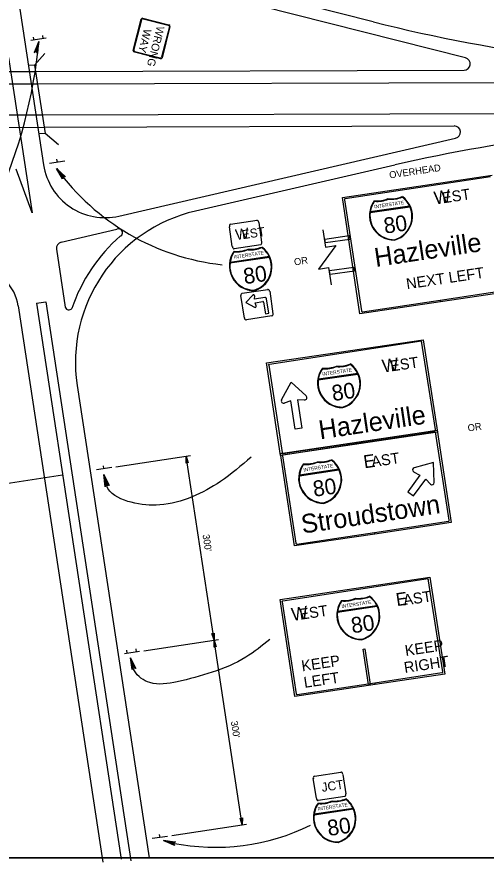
# Model space of a CAD drawing. Extents: x 644898 to 648326, y 298294 to 300670.
# Drawn here: x 647835.4 to 648038.7, y 300089.7 to 300456 of the extents above; entities that cross this region are included whole.
import ezdxf

# ---------------------------------------------------------------- set-up
doc = ezdxf.new("R2010")
doc.units = 0
doc.layers.add('1', color=7, linetype='Continuous')
doc.layers.add('2', color=7, linetype='Continuous')

msp = doc.modelspace()

# ---------------------------------------------------------------- linework, layer by layer
at = {"layer": '1'}
for p, q in [((648247.32, 300091.49), (647461.32, 300091.49)), ((647461.32, 300091.49), (648047.32, 300091.49))]:
    msp.add_line(p, q, dxfattribs=at)
at = {"layer": '2'}
for p, q in [((647989.82, 300453.87), (647844.32, 300490.74)), ((648029.82, 300438.24), (647855.82, 300482.24)), ((647835.95, 300464.24), (647846.95, 300391.87)), ((647885.82, 300441.37), (647889.2, 300454.99)), ((647886.07, 300441.49), (647889.45, 300454.87)), ((647889.95, 300455.37), (647901.2, 300452.49)), ((647890.07, 300455.12), (647900.95, 300452.37)), ((647901.45, 300451.74), (647898.07, 300438.49)), ((647901.7, 300451.87), (647898.32, 300438.24)), ((647848.07, 300446.74), (647841.45, 300445.74)), ((647842.82, 300445.87), (647842.57, 300447.24)), ((647846.82, 300446.49), (647846.57, 300447.87)), ((647893.7, 300446.62), (647893.7, 300446.62)), ((647831.79, 300438.36), (647842.02, 300371.06)), ((647847.45, 300440.12), (647843.07, 300434.99)), ((647897.57, 300437.87), (647886.32, 300440.74)), ((647897.45, 300438.12), (647886.45, 300440.87)), ((647843.07, 300434.99), (647840.4, 300434.97)), ((647843.07, 300434.99), (647847.57, 300405.49)), ((647817.8, 300432.33), (647843.57, 300432.37)), ((647840.82, 300432.37), (647840.82, 300432.37)), ((647843.57, 300432.37), (648029.2, 300432.87)), ((647818.62, 300426.96), (647844.32, 300426.99)), ((647844.32, 300426.99), (648247.32, 300428.13)), ((647820.68, 300413.46), (647846.32, 300413.49)), ((647846.32, 300413.49), (648247.32, 300414.76)), ((647847.2, 300408.12), (648024.95, 300408.74)), ((647821.5, 300408.09), (647847.2, 300408.12)), ((647836.32, 300408.12), (647836.32, 300408.12)), ((647844.45, 300408.12), (647844.45, 300408.12)), ((647847.57, 300405.49), (647844.91, 300405.31)), ((647853.45, 300400.49), (647847.57, 300405.49)), ((647879.57, 300369.62), (648025.45, 300403.37)), ((647852.95, 300392.99), (647852.7, 300394.37)), ((647856.2, 300393.49), (647849.57, 300392.49)), ((647912.82, 300371.87), (647999.2, 300391.87)), ((647842.02, 300371.06), (647835, 300390.04)), ((647976.44, 300377.72), (648041.41, 300387.38)), ((647984.05, 300327.32), (647976.43, 300377.72)), ((647977.35, 300376.73), (647984.69, 300328.54)), ((647990.41, 300376.05), (647990.41, 300376.05)), ((647996.42, 300376.97), (647996.42, 300376.97)), ((648002.34, 300377.86), (648002.34, 300377.86)), ((647988.51, 300371.18), (648005.65, 300373.72)), ((648005.58, 300373.99), (647988.54, 300371.47)), ((647928.7, 300356.49), (647927.45, 300364.99)), ((647927.95, 300366.12), (647939.45, 300367.87)), ((647940.2, 300366.87), (647941.45, 300358.37)), ((647854.57, 300358.37), (647878.7, 300363.99)), ((647934.45, 300361.62), (647934.45, 300361.62)), ((647967.99, 300363.64), (647969.12, 300356.22)), ((647967.99, 300363.64), (647969.12, 300356.22)), ((647941.07, 300357.24), (647929.57, 300355.49)), ((647852.57, 300355.37), (647856.32, 300330.12)), ((647929.7, 300354.24), (647929.7, 300354.24)), ((647935.57, 300355.12), (647935.57, 300355.12)), ((647941.45, 300355.99), (647941.45, 300355.99)), ((647927.7, 300349.37), (647944.82, 300351.87)), ((647944.7, 300352.12), (647927.82, 300349.49)), ((647936.95, 300346.37), (647936.95, 300346.37)), ((647970.48, 300347.32), (647971.61, 300339.91)), ((647933.95, 300325.49), (647932.45, 300335.24)), ((647933.95, 300325.49), (647932.45, 300335.24)), ((647933.07, 300336.24), (647944.07, 300337.87)), ((647933.07, 300336.24), (647944.07, 300337.87)), ((647937.57, 300335.37), (647934.57, 300332.24)), ((647944.95, 300337.12), (647946.32, 300327.37)), ((647944.95, 300337.12), (647946.32, 300327.37)), ((648018.78, 300333.23), (648047.9, 300337.67)), ((648049.11, 300337), (648018.89, 300332.5)), ((647843.83, 300331.92), (647847.96, 300332.54)), ((647843.83, 300331.92), (647880.58, 300090.92)), ((647847.96, 300332.54), (647884.79, 300090.29)), ((647934.57, 300332.24), (647938.32, 300330.12)), ((647938.32, 300333.62), (647938.45, 300335.12)), ((647942.82, 300334.37), (647938.32, 300333.62)), ((647938.7, 300332.12), (647941.95, 300332.62)), ((647939.07, 300330.74), (647938.7, 300332.12)), ((647942.2, 300332.37), (647943.07, 300327.37)), ((647943.57, 300333.74), (647943.57, 300333.74)), ((647944.57, 300327.62), (647943.57, 300333.74)), ((648018.89, 300332.5), (647984.05, 300327.32)), ((647985.09, 300328.16), (648018.78, 300333.23)), ((648018.89, 300332.5), (648018.78, 300333.23)), ((648018.78, 300333.23), (648018.89, 300332.5)), ((647835.92, 300330.71), (647872.67, 300089.71)), ((647939.45, 300331.24), (647939.45, 300331.24)), ((647939.45, 300331.24), (647939.45, 300331.24)), ((647945.82, 300326.37), (647934.82, 300324.74)), ((647945.82, 300326.37), (647934.82, 300324.74)), ((647943.07, 300327.37), (647944.57, 300327.62)), ((647943.58, 300306.01), (648011.47, 300316.1)), ((648016.79, 300277.11), (648010.75, 300315.43)), ((648011.47, 300316.1), (648017.64, 300276.08)), ((647949.66, 300265.97), (647943.58, 300306.02)), ((647944.49, 300305.02), (647950.3, 300267.2)), ((647967.89, 300303.5), (647967.89, 300303.5)), ((647973.9, 300304.42), (647973.9, 300304.42)), ((647966, 300298.64), (647983.13, 300301.18)), ((647983.07, 300301.45), (647966.02, 300298.93)), ((647861.57, 300296.24), (647892.7, 300091.49)), ((647950.06, 300290.1), (647954.3, 300297.69)), ((647954.3, 300297.69), (647960.71, 300291.71)), ((647954.1, 300289.6), (647951.26, 300288.53)), ((647955.92, 300277.3), (647954.1, 300289.6)), ((647956.97, 300290.01), (647958.8, 300277.73)), ((647960.1, 300289.95), (647956.97, 300290.01)), ((647949.55, 300266.74), (648017.51, 300276.84)), ((647958.8, 300277.73), (647955.92, 300277.3)), ((647984.39, 300271.88), (648016.4, 300276.75)), ((648017.51, 300276.84), (648023.6, 300236.81)), ((648017.64, 300276.08), (647984.51, 300271.1)), ((648022.76, 300237.83), (648016.72, 300276.16)), ((647984.5, 300271.15), (647949.66, 300265.97)), ((647950.7, 300266.81), (647984.39, 300271.88)), ((647984.51, 300271.1), (647984.39, 300271.88)), ((647984.39, 300271.88), (647984.5, 300271.15)), ((647878.32, 300260.99), (647910.57, 300265.87)), ((647920.82, 300185.87), (647908.7, 300265.62)), ((647955.62, 300226.7), (647949.55, 300266.74)), ((647950.46, 300265.75), (647956.26, 300227.93)), ((647959.73, 300262.03), (647959.73, 300262.03)), ((647965.73, 300262.95), (647965.73, 300262.95)), ((648015.96, 300262.92), (648007.5, 300260.63)), ((648016.19, 300254.23), (648015.96, 300262.92)), ((647867.2, 300259.24), (647867.2, 300259.24)), ((647876.45, 300260.74), (647869.82, 300259.74)), ((647873.07, 300260.24), (647872.95, 300261.49)), ((647957.83, 300257.16), (647974.96, 300259.7)), ((647974.9, 300259.97), (647957.85, 300257.45)), ((648007.28, 300258.8), (648010.02, 300257.43)), ((647762.2, 300243.37), (647855.07, 300257.49)), ((648010.02, 300257.43), (648004.85, 300250.15)), ((648007.21, 300248.37), (648012.53, 300255.6)), ((648012.53, 300255.6), (648014.59, 300253.54)), ((648004.85, 300250.15), (648007.21, 300248.37)), ((647990.36, 300232.61), (648022.37, 300237.48)), ((648023.6, 300236.81), (647990.47, 300231.83)), ((647990.47, 300231.88), (647955.62, 300226.7)), ((647956.66, 300227.54), (647990.36, 300232.61)), ((647990.47, 300231.83), (647990.36, 300232.61)), ((647990.36, 300232.61), (647990.47, 300231.88)), ((647949.4, 300203.48), (648014.37, 300213.14)), ((648019.99, 300172.14), (648013.65, 300212.47)), ((648014.37, 300213.14), (648020.83, 300171.13)), ((647955.77, 300161.45), (647949.4, 300203.49)), ((647982.25, 300203.79), (647982.25, 300203.79)), ((647950.31, 300202.5), (647956.47, 300162.68)), ((647974.35, 300198.01), (647991.48, 300200.55)), ((647991.42, 300200.81), (647974.37, 300198.29)), ((647976.24, 300202.87), (647976.24, 300202.87)), ((647890.45, 300181.24), (647922.7, 300186.24)), ((647933.07, 300105.87), (647920.82, 300185.87)), ((647883.2, 300180.24), (647883.07, 300181.49)), ((647887.2, 300180.74), (647887.07, 300182.12)), ((647879.32, 300179.62), (647879.32, 300179.62)), ((647888.57, 300180.99), (647881.95, 300179.99)), ((647990.51, 300167.36), (648019.6, 300171.86)), ((648020.83, 300171.13), (647990.62, 300166.63)), ((647956.82, 300162.28), (647990.51, 300167.36)), ((647990.62, 300166.63), (647990.51, 300167.36)), ((647990.51, 300167.36), (647990.62, 300166.63)), ((647990.62, 300166.63), (647955.77, 300161.45)), ((647964.32, 300126.99), (647975.82, 300128.74)), ((647976.57, 300127.74), (647977.95, 300119.24)), ((647965.2, 300117.37), (647963.82, 300125.87)), ((647970.82, 300122.49), (647970.82, 300122.49)), ((647977.45, 300118.12), (647965.95, 300116.37)), ((647971.95, 300115.99), (647971.95, 300115.99)), ((647977.95, 300116.87), (647977.95, 300116.87)), ((647981.07, 300112.99), (647964.2, 300110.49)), ((647964.2, 300110.24), (647981.2, 300112.74)), ((647966.07, 300115.12), (647966.07, 300115.12)), ((647902.57, 300101.24), (647934.95, 300106.12)), ((647900.7, 300100.87), (647894.07, 300099.87)), ((647897.45, 300100.37), (647897.2, 300101.74)), ((647891.45, 300099.87), (647891.45, 300099.87)), ((647891.45, 300099.49), (647891.45, 300099.49))]:
    msp.add_line(p, q, dxfattribs=at)
for points in [[(647844.23, 300440.45), (647843.9, 300440.76), (647844.89, 300445.34), (647844.23, 300440.45), (647844.44, 300440.16), (647844.89, 300445.34), (647843.52, 300440.82), (647843.13, 300440.76), (647844.89, 300445.34), (647842.84, 300440.55), (647843.13, 300440.76)], [(647855.2, 300386.12), (647855.32, 300386.49), (647852.57, 300390.24), (647855.2, 300386.12), (647855.2, 300385.74), (647852.57, 300390.24), (647855.7, 300386.74), (647856.07, 300386.87), (647852.57, 300390.24), (647856.45, 300386.74), (647856.07, 300386.87)], [(648040.68, 300386.7), (647977.64, 300377.08)], [(647969.12, 300356.22), (647973.57, 300356.9), (647966.03, 300346.65), (647970.48, 300347.32)], [(648010.75, 300315.43), (647944.78, 300305.37)], [(648016.71, 300276.16), (647950.75, 300266.1)], [(647908.77, 300262.74), (647908.96, 300262.88), (647908.7, 300265.62), (647908.77, 300262.74), (647908.67, 300262.58), (647908.7, 300265.62), (647909.25, 300262.93), (647909.46, 300262.86), (647908.7, 300265.62), (647909.62, 300262.73), (647909.46, 300262.86)], [(647873.82, 300252.74), (647874.07, 300252.99), (647873.07, 300257.62), (647873.82, 300252.74), (647873.7, 300252.37), (647873.07, 300257.62), (647874.57, 300253.12), (647874.95, 300253.12), (647873.07, 300257.62), (647875.32, 300252.87), (647874.95, 300253.12)], [(648013.65, 300212.47), (647950.6, 300202.85)], [(647920.75, 300188.74), (647920.56, 300188.61), (647920.82, 300185.87), (647920.75, 300188.74), (647920.85, 300188.91), (647920.82, 300185.87), (647920.28, 300188.56), (647920.06, 300188.63), (647920.82, 300185.87), (647919.9, 300188.76), (647920.06, 300188.63)], [(647920.9, 300182.99), (647921.09, 300183.13), (647920.82, 300185.87), (647920.9, 300182.99), (647920.8, 300182.83), (647920.82, 300185.87), (647921.37, 300183.18), (647921.59, 300183.11), (647920.82, 300185.87), (647921.75, 300182.98), (647921.59, 300183.11)], [(647885.45, 300173.37), (647885.82, 300173.62), (647884.57, 300178.24), (647885.45, 300173.37), (647885.32, 300173.12), (647884.57, 300178.24), (647886.2, 300173.87), (647886.57, 300173.74), (647884.57, 300178.24), (647886.95, 300173.62), (647886.57, 300173.74)], [(647933, 300108.75), (647932.81, 300108.61), (647933.07, 300105.87), (647933, 300108.75), (647933.1, 300108.91), (647933.07, 300105.87), (647932.52, 300108.56), (647932.31, 300108.63), (647933.07, 300105.87), (647932.15, 300108.76), (647932.31, 300108.63)], [(647903.52, 300097.23), (647903.4, 300097.61), (647898.97, 300099.03), (647903.52, 300097.23), (647903.74, 300096.93), (647898.97, 300099.03), (647903.55, 300098.03), (647903.78, 300098.35), (647898.97, 300099.03), (647904.16, 300098.47), (647903.78, 300098.35)]]:
    msp.add_lwpolyline(points, dxfattribs=at)
for points in [[(647979.6, 300359.56), (647969.06, 300358), (647968.8, 300359.71), (647979.35, 300361.28)], [(647981.64, 300345.86), (647971.09, 300344.3), (647970.84, 300346.01), (647981.38, 300347.58)], [(647988.52, 300166.77), (647987.69, 300166.64), (647985.4, 300182.05), (647986.23, 300182.17)]]:
    msp.add_lwpolyline(points, close=True, dxfattribs=at)
for centre, radius, start, end in [((648154.92, 301105.15), 671.88, 255.77937, 270.1682), ((647629.05, 300465.34), 216.77, 316.8838, 354.7037), ((648029.16, 300435.59), 2.69, 270.1683, 75.7793), ((648150.55, 299737.19), 671.88, 90.1683, 103.0152), ((648024.9, 300406.01), 2.69, 283.0152, 90.1683), ((647873.54, 300395.85), 26.87, 188.6538, 283.0152), ((647935.45, 300450.26), 102.28, 215.9181, 263.7348), ((647927.94, 300306.37), 67.19, 103.0152, 188.6538), ((647927.94, 300306.37), 72.56, 131.1224, 161.2817), ((647879.49, 300362.47), 1.67, 290.9294, 117.2399), ((647855.18, 300355.75), 2.69, 103.0154, 188.6538), ((647938.18, 300348.07), 10.73, 143.6538, 270.5237), ((647938.18, 300348.07), 10.51, 144.3462, 171.8611), ((647930.74, 300366.7), 12.33, 264.4038, 292.9038), ((647930.74, 300366.7), 12.56, 264.9943, 292.6428), ((647936.74, 300367.61), 12.33, 264.4038, 292.9038), ((647936.74, 300367.61), 12.56, 264.6648, 292.3133), ((647935.18, 300347.61), 10.73, 286.7839, 53.6538), ((647935.18, 300347.61), 10.51, 25.4466, 52.9614), ((647935.18, 300347.61), 10.51, 286.7839, 24.1669), ((647816.01, 300327.69), 20.16, 8.6538, 80.3831), ((647938.18, 300348.07), 10.51, 173.1407, 270.5237), ((647937.91, 300335.08), 0.502, 358.1291, 138.7947), ((647941.98, 300332.36), 0.269, 8.6538, 98.6538), ((647942.92, 300333.68), 0.672, 8.6538, 98.6538), ((647857.91, 300330.62), 1.63, 197.7979, 323.4245), ((647938.62, 300330.59), 0.502, 236.4996, 20.4062), ((648007.75, 300259.69), 0.915, 103.9183, 245.5492), ((648015.29, 300254.14), 0.915, 225, 1.3737), ((647967.13, 300127.58), 12.33, 264.4038, 292.9038), ((647967.13, 300127.58), 12.56, 264.9943, 292.6428), ((647973.14, 300128.49), 12.33, 264.4038, 292.9038), ((647973.14, 300128.49), 12.56, 264.6648, 292.3133), ((647971.57, 300108.49), 10.73, 286.7839, 53.6538), ((647971.57, 300108.49), 10.51, 25.4466, 52.9614), ((647974.58, 300108.95), 10.73, 143.6538, 270.5237), ((647974.58, 300108.95), 10.51, 144.3462, 171.8611), ((647971.57, 300108.49), 10.51, 286.7839, 24.1669), ((647974.58, 300108.95), 10.51, 173.1407, 270.5237), ((647921.32, 300190.06), 93.92, 258.636, 296.1278)]:
    msp.add_arc(centre, radius, start, end, dxfattribs=at)
for centre, major_axis, ratio, start_param, end_param in [((647889.85, 300454.88), (-0.625, 0.158), 0.777833, 4.712389, 6.283185), ((647890, 300454.69), (-0.578, 0.147), 0.777833, 4.712389, 6.283185), ((647900.88, 300451.93), (-0.578, 0.147), 0.777833, 3.141593, 4.712389), ((647901.1, 300452.02), (-0.625, 0.158), 0.777833, 3.141593, 4.712389), ((647886.4, 300441.26), (0.625, -0.158), 0.777833, 3.141593, 4.712389), ((647886.62, 300441.36), (0.578, -0.147), 0.777833, 3.141593, 4.712389), ((647897.5, 300438.6), (0.578, -0.147), 0.777833, 4.712389, 6.283185), ((647897.65, 300438.41), (0.625, -0.158), 0.777833, 4.712389, 6.283185), ((647977.67, 300376.76), (-0.388, 0), 0.989072, 4.856969, 6.450662), ((647999, 300369.94), (-10.85, 0), 0.989072, 5.647198, 7.861496), ((647999, 300369.94), (-10.62, 0), 0.989072, 5.659282, 6.139508), ((647991.51, 300388.58), (-12.46, 0), 0.989072, 1.471498, 1.968918), ((647991.51, 300388.58), (-12.69, 0), 0.989072, 1.481804, 1.964361), ((647997.58, 300389.48), (12.46, 0), 0.989072, 4.61309, 5.11051), ((647997.58, 300389.48), (12.69, 0), 0.989072, 4.617647, 5.100204), ((647995.97, 300369.48), (10.85, 0), 0.989072, 5.003697, 7.217995), ((647995.97, 300369.48), (10.62, 0), 0.989072, 0.4425, 0.922725), ((647995.97, 300369.48), (10.62, 0), 0.989072, 5.003697, 6.703352), ((647999, 300369.94), (-10.62, 0), 0.989072, 6.161841, 7.861496), ((647928.1, 300365.04), (0.16, -1.06), 0.6, 3.141593, 4.712389), ((647939.58, 300366.79), (-0.16, 1.06), 0.6, 4.712389, 6.283185), ((647940.87, 300358.29), (-0.16, 1.06), 0.6, 3.141593, 4.712389), ((647929.4, 300356.54), (0.16, -1.06), 0.6, 4.712389, 6.283185), ((647933.2, 300335.3), (0.14, -0.921), 0.769266, 3.141593, 4.712389), ((647933.2, 300335.3), (0.14, -0.921), 0.769266, 3.141593, 4.712389), ((647944.19, 300336.98), (-0.14, 0.921), 0.769266, 4.712389, 6.283185), ((647944.19, 300336.98), (-0.14, 0.921), 0.769266, 4.712389, 6.283185), ((647985.05, 300328.57), (-0.402, -0.077), 0.953585, 6.234444, 7.82518), ((647934.67, 300325.63), (0.14, -0.921), 0.769266, 4.712389, 6.283185), ((647934.67, 300325.63), (0.14, -0.921), 0.769266, 4.712389, 6.283185), ((647945.66, 300327.3), (-0.14, 0.921), 0.769266, 3.141593, 4.712389), ((647945.66, 300327.3), (-0.14, 0.921), 0.769266, 3.141593, 4.712389), ((648010.5, 300314.89), (-0.386, 0), 0.994065, 3.283634, 4.860778), ((647944.82, 300305.05), (-0.388, 0), 0.989072, 4.856969, 6.450662), ((647976.49, 300297.39), (-10.85, 0), 0.989072, 5.647198, 7.861496), ((647976.49, 300297.39), (-10.62, 0), 0.989072, 5.659282, 6.139508), ((647969, 300316.03), (-12.46, 0), 0.989072, 1.471498, 1.968918), ((647969, 300316.03), (-12.69, 0), 0.989072, 1.481804, 1.964361), ((647975.06, 300316.94), (12.46, 0), 0.989072, 4.61309, 5.11051), ((647975.06, 300316.94), (12.69, 0), 0.989072, 4.617647, 5.100204), ((647973.45, 300296.94), (10.85, 0), 0.989072, 5.003697, 7.217995), ((647973.45, 300296.94), (10.62, 0), 0.989072, 0.4425, 0.922725), ((647976.49, 300297.39), (-10.62, 0), 0.989072, 6.161841, 7.861496), ((647973.45, 300296.94), (10.62, 0), 0.989072, 5.003697, 6.703352), ((647960.04, 300290.96), (-0.02, 1.02), 0.989072, 3.073775, 5.58542), ((647950.97, 300289.58), (-0.02, 1.02), 0.989072, 1.007506, 3.462583), ((648016.38, 300277.06), (0.395, 0.011), 0.92315, 4.838085, 6.411533), ((648016.46, 300275.62), (-0.386, 0), 0.994065, 3.283634, 4.860778), ((647950.65, 300267.24), (-0.352, -0.214), 0.980321, 5.879464, 7.4702), ((647950.78, 300265.78), (-0.388, 0), 0.989072, 4.856969, 6.450662), ((647968.32, 300255.92), (-10.85, 0), 0.989072, 5.647198, 7.861496), ((647968.32, 300255.92), (-10.62, 0), 0.989072, 5.659282, 6.139508), ((647960.83, 300274.56), (-12.46, 0), 0.989072, 1.471498, 1.968918), ((647960.83, 300274.56), (-12.69, 0), 0.989072, 1.481804, 1.964361), ((647966.89, 300275.46), (12.46, 0), 0.989072, 4.61309, 5.11051), ((647966.89, 300275.46), (12.69, 0), 0.989072, 4.617647, 5.100204), ((647965.28, 300255.46), (10.85, 0), 0.989072, 5.003697, 7.217995), ((647965.28, 300255.46), (10.62, 0), 0.989072, 0.4425, 0.922725), ((647965.28, 300255.46), (10.62, 0), 0.989072, 5.003697, 6.703352), ((647968.32, 300255.92), (-10.62, 0), 0.989072, 6.161841, 7.861496), ((648022.34, 300237.78), (0.395, 0.011), 0.92315, 4.838085, 6.411533), ((647956.62, 300227.97), (-0.352, -0.214), 0.980321, 5.879464, 7.4702), ((648013.39, 300211.93), (-0.388, 0), 0.989072, 3.283634, 4.860778), ((647977.34, 300215.4), (-12.46, 0), 0.989072, 1.471498, 1.968918), ((647977.34, 300215.4), (-12.69, 0), 0.989072, 1.481804, 1.964361), ((647983.41, 300216.3), (12.46, 0), 0.989072, 4.61309, 5.11051), ((647983.41, 300216.3), (12.69, 0), 0.989072, 4.617647, 5.100204), ((647981.8, 300196.31), (10.85, 0), 0.989072, 5.003697, 7.217995), ((647981.8, 300196.31), (10.62, 0), 0.989072, 0.4425, 0.922725), ((647950.64, 300202.52), (-0.388, 0), 0.989072, 4.856969, 6.450662), ((647984.84, 300196.76), (-10.85, 0), 0.989072, 5.647198, 7.861496), ((647984.84, 300196.76), (-10.62, 0), 0.989072, 5.659282, 6.139508), ((647981.8, 300196.31), (10.62, 0), 0.989072, 5.003697, 6.703352), ((647984.84, 300196.76), (-10.62, 0), 0.989072, 6.161841, 7.861496), ((648019.57, 300172.1), (0.402, 0.003), 0.738398, 4.858425, 6.431874), ((647956.78, 300162.72), (-0.025, -0.422), 0.860447, 4.912896, 6.503633), ((647964.49, 300125.92), (0.16, -1.06), 0.6, 3.141593, 4.712389), ((647975.97, 300127.67), (-0.16, 1.06), 0.6, 4.712389, 6.283185), ((647977.27, 300119.16), (-0.16, 1.06), 0.6, 3.141593, 4.712389), ((647965.79, 300117.42), (0.16, -1.06), 0.6, 4.712389, 6.283185)]:
    msp.add_ellipse(centre, major_axis=major_axis, ratio=ratio, start_param=start_param, end_param=end_param, dxfattribs=at)
for points in [[(647936.95, 300265.24), (647923.57, 300254.62), (647911.32, 300247.99), (647897.32, 300244.49), (647884.95, 300245.62), (647874.82, 300251.62), (647873.07, 300257.62)], [(647944.95, 300186.24), (647934.57, 300178.49), (647919.95, 300171.99), (647904.82, 300167.87), (647892.95, 300167.49), (647886.32, 300172.62), (647884.57, 300178.24)]]:
    msp.add_spline(points, degree=3, dxfattribs=at)

# ---------------------------------------------------------------- texts
for s, height, rotation, p in [('WAY', 3.386, 255.7793, (647890.45, 300450.99)), ('WRONG', 3.385, 255.7793, (647896.07, 300452.24)), ('OVERHEAD', 3, 8.3729, (647996.96, 300385.95)), ('W', 5.63, 8.4837, (648016.58, 300374.65)), ('EST', 4.719, 8.4705, (648020, 300375.16)), ('INTERSTATE', 1.517, 8.469, (647990.34, 300372.94)), ('80', 6.829, 8.468, (647994.87, 300362.02)), ('W', 4.63, 8.6525, (647930.45, 300359.24)), ('EST', 3.875, 8.6538, (647933.2, 300359.62)), ('Hazleville', 8.168, 8.4705, (647990.9, 300347.59)), ('INTERSTATE', 1.517, 8.6538, (647929.57, 300351.12)), ('OR', 3, 8.6282, (647955.72, 300348.26)), ('80', 6.829, 8.6538, (647934.07, 300340.12)), ('NEXT LEFT', 4.719, 8.4705, (648004.45, 300337.92)), ('W', 5.63, 8.4837, (647994.1, 300301.79)), ('EST', 4.719, 8.4705, (647997.52, 300302.3)), ('INTERSTATE', 1.517, 8.469, (647967.83, 300300.4)), ('80', 6.829, 8.468, (647972.36, 300289.47)), ('Hazleville', 8.168, 8.4705, (647966.78, 300272.89)), ('OR', 3, 8.6282, (648030.97, 300276.29)), ('E', 5.63, 8.4837, (647986.01, 300260.32)), ('AST', 4.719, 8.4705, (647989.35, 300260.82)), ('INTERSTATE', 1.517, 8.469, (647959.66, 300258.92)), ('80', 6.829, 8.468, (647964.19, 300248)), ('Stroudstown', 8.1676, 8.4705, (647959.19, 300232.04)), ("300'", 3, 278.6536, (647915.82, 300231.53)), ('AST', 4.719, 8.4705, (648003.18, 300200.9)), ('E', 5.63, 8.4837, (648000.06, 300200.6)), ('W', 5.63, 8.4837, (647954.78, 300194.19)), ('EST', 4.719, 8.4705, (647958.19, 300194.7)), ('INTERSTATE', 1.517, 8.469, (647976.17, 300199.76)), ('80', 6.829, 8.468, (647980.71, 300188.84)), ('KEEP', 4.719, 8.4705, (648003.89, 300179)), ('KEEP', 4.719, 8.4705, (647959.04, 300172.34)), ('RIGHT', 4.719, 8.4705, (648003.49, 300171.64)), ('LEFT', 4.719, 8.4705, (647960.05, 300165.19)), ("300'", 3, 278.6537, (647928.07, 300150.66)), ('JCT', 3.896, 8.6538, (647967.7, 300120.12)), ('INTERSTATE', 1.517, 8.6538, (647965.95, 300111.99)), ('80', 6.829, 8.6538, (647970.45, 300100.99))]:
    msp.add_text(s, height=height, rotation=rotation, dxfattribs=at).set_placement(p)

doc.saveas('drawing.dxf')
